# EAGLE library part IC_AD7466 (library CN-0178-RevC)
1.6V -3.6V Micropower, successive approximation, 200kSPS 12-Bit ADC.
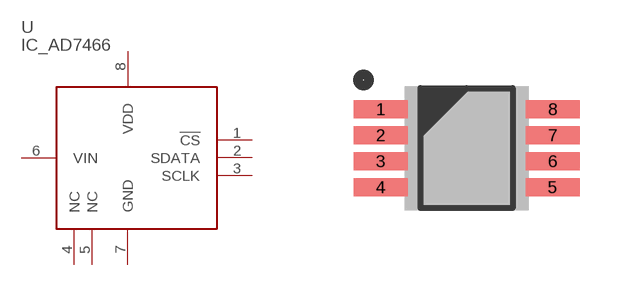
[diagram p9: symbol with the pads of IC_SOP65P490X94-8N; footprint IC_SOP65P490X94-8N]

Designator prefix -

## IC_AD7466_TSSOP8  [IC_SOP65P490X94-8N]
1  !CS  pas
2  SDATA  pas
3  SCLK  pas
4  NC  pas
5  NC  pas
6  VIN  pas
7  GND  pas
8  VDD  pas

## Footprint IC_SOP65P490X94-8N (pad centres in mm)
(TSSOP-8) 0.65mm pitch; 3.00mm W X 3.00mm L X 0.94mm H body; JEDEC-MO-187AA-T
smd 1.35 x 0.45: 1 -2.15,0.975; 2 -2.15,0.325; 3 -2.15,-0.325; 4 -2.15,-0.975; 5 2.15,-0.975; 6 2.15,-0.325; 7 2.15,0.325; 8 2.15,0.975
